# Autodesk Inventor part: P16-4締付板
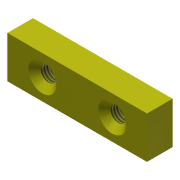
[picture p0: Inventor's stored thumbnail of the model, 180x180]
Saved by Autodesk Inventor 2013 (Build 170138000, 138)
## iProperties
Created: 2008-07
Part Number: P16-4締付板
Document SubType Name: Modeling
Designer: y-shimohigashi
Density: 1 g/cm^3
Material: 一般
Author: y-shimohigashi
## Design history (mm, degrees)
sketch "スケッチ1"
  geometry: L1 (-30, 5.5)-(30, 5.5); L2 (30, 5.5)-(30, -5.5); L3 (30, -5.5)-(-30, -5.5); L4 (-30, -5.5)-(-30, 5.5); L5 (30, 5.5)-(-30, -5.5); 2 further points
  constraints: 10 end point, 2 parallel, 1 coincident, 1 horizontal, 1 midpoint, 1 perpendicular
  dimensions: "d0" = 11 distance of L1.end L2.end; "d1" = 60 distance of L2.end L3.end
extrude "押し出し1" new body sketch "スケッチ1" distance "d2" = 18; taper "d3" = 0 deg
sketch "スケッチ2"
  geometry: L1 (30, -3.6)-(30, 21.6) reference; L2 (60, 0)-(60, 18) reference; 3 further points
  constraints: 1 horizontal alignment, 1 midpoint, 1 symmetric about line
  dimensions: "d4" = 30 distance of point (45, 9) point (15, 9)
hole "穴1" sketch "スケッチ2" at (15, 9), (45, 9) diameter "d5" = 6.647; stored, may be unused: countersink angle "d9" = 90 deg, drill point angle "d11" = 118 deg; dims "d6" = 6, "d7" = 12, "d8" = 2, "d10" = 8
node "ソリッド1"
node "ソリッド ボディ"
node "サーフェス ボディ"
